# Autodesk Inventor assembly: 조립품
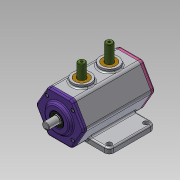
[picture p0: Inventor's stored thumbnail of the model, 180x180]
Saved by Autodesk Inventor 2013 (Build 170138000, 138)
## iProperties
Created: 2021-06
Part Number: 조립품
Document SubType Name: Assembly
Designer: hana-cad17
Author: hana-cad17
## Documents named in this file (11)
- C:\Documents and Settings\hana-cad17\바탕 화면\710606V1022\조립품.iam
- C:\Documents and Settings\hana-cad17\바탕 화면\710606V1022\본체.ipt
- C:\Documents and Settings\hana-cad17\바탕 화면\710606V1022\앞커버.ipt
- C:\Documents and Settings\hana-cad17\바탕 화면\710606V1022\뒷커버.ipt
- C:\Documents and Settings\hana-cad17\바탕 화면\710606V1022\부시.ipt
- C:\Documents and Settings\hana-cad17\바탕 화면\710606V1022\오일실.ipt
- C:\Documents and Settings\hana-cad17\바탕 화면\710606V1022\베어링 6203.ipt
- C:\Documents and Settings\hana-cad17\바탕 화면\710606V1022\편심축.ipt
- C:\Documents and Settings\hana-cad17\바탕 화면\710606V1022\베어링 6302.ipt
- C:\Documents and Settings\hana-cad17\바탕 화면\710606V1022\슬라이더.ipt
- C:\Documents and Settings\hana-cad17\바탕 화면\710606V1022\볼트 M4.ipt
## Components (10 placed, 3 different names)
1. 8-오일실:1
2. 7-베어링 6203:1
3. 9-M4-소켓머리:1
4. 9-M4-소켓머리:2
5. 9-M4-소켓머리:3
6. 9-M4-소켓머리:4
7. 9-M4-소켓머리:5
8. 9-M4-소켓머리:6
9. 9-M4-소켓머리:7
10. 9-M4-소켓머리:8
